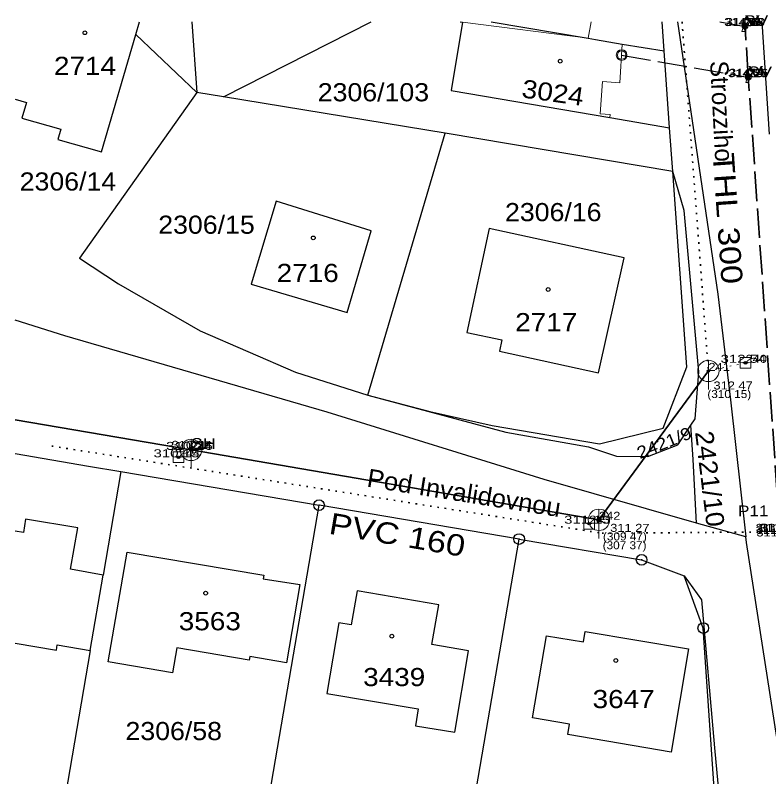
# Model space of a CAD drawing. Extents: x -652394 to -652006, y -1024262 to -1023975.
# Drawn here: x -652393.6 to -652323, y -1024046.7 to -1023975.3 of the extents above; entities that cross this region are included whole.
import ezdxf
from ezdxf.enums import TextEntityAlignment as Align

# ---------------------------------------------------------------- set-up
doc = ezdxf.new("R2010")
doc.units = 0
doc.header["$LTSCALE"] = 0.46
doc.header["$PDMODE"] = 32
doc.header["$PDSIZE"] = 0.23
doc.linetypes.add('DOTTED', pattern=[1.5, 0.3, -1.2])
doc.linetypes.add('LONG_DASHED', pattern=[7.5, 6, -1.5])
for name, color, linetype in [('1', 7, 'Continuous'), ('17', 7, 'Continuous'), ('18', 7, 'Continuous'), ('2', 7, 'Continuous'), ('3', 7, 'Continuous'), ('4', 7, 'Continuous')]:
    doc.layers.add(name, color=color, linetype=linetype)
for name, color, linetype, lineweight in [('10', 7, 'Continuous', 13), ('12', 7, 'Continuous', 13), ('35', 7, 'LONG_DASHED', 35), ('36', 7, 'DOTTED', 35), ('45', 7, 'Continuous', 35), ('46', 7, 'DOTTED', 35), ('50', 7, 'LONG_DASHED', 25), ('63', 7, 'Continuous', 25)]:
    doc.layers.add(name, color=color, linetype=linetype, lineweight=lineweight)

msp = doc.modelspace()

# ---------------------------------------------------------------- linework, layer by layer
at = {"layer": '1'}
for p in [(-652325.34, -1023976.33), (-652325.2, -1023976.32), (-652324.98, -1023981.12), (-652324.89, -1023981.08), (-652325.15, -1024007.88), (-652328.63, -1024008.64), (-652377.1, -1024015.94), (-652377.08, -1024016.04), (-652378.26, -1024016.73), (-652339.8, -1024022.95), (-652338.88, -1024022.59)]:
    msp.add_point(p, dxfattribs=at)
at = {"layer": '10'}
for p, q in [((-652328.63, -1024007.64), (-652328.63, -1024010.388)), ((-652324.9, -1024007.88), (-652325.4, -1024007.88)), ((-652377.08, -1024015.04), (-652377.08, -1024017.788)), ((-652378.01, -1024016.73), (-652378.51, -1024016.73)), ((-652338.88, -1024021.59), (-652338.88, -1024024.338)), ((-652339.55, -1024022.95), (-652340.05, -1024022.95))]:
    msp.add_line(p, q, dxfattribs=at)
for points in [[(-652325.19, -1023976.83), (-652325.49, -1023975.83), (-652325.19, -1023975.83), (-652325.49, -1023976.83)], [(-652324.83, -1023981.62), (-652325.13, -1023980.62), (-652324.83, -1023980.62), (-652325.13, -1023981.62)], [(-652324.65, -1024007.38), (-652325.65, -1024007.38), (-652325.65, -1024008.38), (-652324.65, -1024008.38)], [(-652377.76, -1024016.23), (-652378.76, -1024016.23), (-652378.76, -1024017.23), (-652377.76, -1024017.23)], [(-652339.3, -1024022.45), (-652340.3, -1024022.45), (-652340.3, -1024023.45), (-652339.3, -1024023.45)]]:
    msp.add_lwpolyline(points, close=True, dxfattribs=at)
for centre in [(-652328.63, -1024008.641), (-652377.08, -1024016.041), (-652338.88, -1024022.591)]:
    msp.add_circle(centre, 1.0002, dxfattribs=at)
at = {"layer": '12'}
for centre, radius in [((-652325.2, -1023976.32), 0.3), ((-652325.2, -1023976.32), 0.2), ((-652325.2, -1023976.32), 0.1), ((-652336.754, -1023979.044), 0.5), ((-652336.754, -1023979.044), 0.4), ((-652324.89, -1023981.08), 0.3), ((-652324.89, -1023981.08), 0.2), ((-652324.89, -1023981.08), 0.1)]:
    msp.add_circle(centre, radius, dxfattribs=at)
at = {"layer": '35'}
msp.add_line((-652325.2, -1023976.32), (-652325.218, -1023975.941), dxfattribs=at)
msp.add_lwpolyline([(-652321.94, -1024023.7), (-652324.89, -1023981.08), (-652325.2, -1023976.32)], dxfattribs=at)
at = {"layer": '36'}
msp.add_lwpolyline([(-652390.132, -1024015.68), (-652338.593, -1024023.847), (-652322.39, -1024023.72)], dxfattribs=at)
at = {"layer": '45'}
for p, q in [((-652328.63, -1024008.64), (-652338.88, -1024022.59)), ((-652377.08, -1024016.04), (-652393.553, -1024013.212)), ((-652338.88, -1024022.59), (-652377.08, -1024016.04))]:
    msp.add_line(p, q, dxfattribs=at)
at = {"layer": '46'}
msp.add_line((-652331.095, -1023975.941), (-652328.63, -1024008.64), dxfattribs=at)
at = {"layer": '50'}
for p, q in [((-652327.547, -1023975.941), (-652325.34, -1023976.33)), ((-652325.34, -1023976.33), (-652325.2, -1023976.32)), ((-652336.754, -1023979.044), (-652324.98, -1023981.12)), ((-652324.89, -1023981.08), (-652324.98, -1023981.12))]:
    msp.add_line(p, q, dxfattribs=at)
at = {"layer": '50', "linetype": 'DOTTED', "lineweight": 13}
for p, q in [((-652325.15, -1024007.88), (-652328.63, -1024008.64)), ((-652378.26, -1024016.73), (-652377.08, -1024016.04)), ((-652339.8, -1024022.95), (-652338.88, -1024022.59))]:
    msp.add_line(p, q, dxfattribs=at)
at = {"layer": '63'}
for p, q in [((-652382.27, -1023977.13), (-652381.922, -1023975.941)), ((-652377.024, -1023975.941), (-652376.54, -1023982.54)), ((-652374.06, -1023982.95), (-652360.225, -1023975.941)), ((-652332.78, -1023978.64), (-652332.971, -1023975.941)), ((-652322.92, -1023986.45), (-652323.6, -1023975.941)), ((-652382.27, -1023977.13), (-652376.54, -1023982.54)), ((-652332.26, -1023985.85), (-652332.78, -1023978.64)), ((-652376.54, -1023982.54), (-652387.54, -1023998.06)), ((-652374.06, -1023982.95), (-652376.54, -1023982.54)), ((-652353.29, -1023986.36), (-652374.06, -1023982.95)), ((-652331.96, -1023989.97), (-652332.26, -1023985.85)), ((-652360.54, -1024010.92), (-652353.29, -1023986.36)), ((-652331.96, -1023989.97), (-652353.29, -1023986.36)), ((-652330.06, -1024016.95), (-652330.27, -1024013.72)), ((-652383.67, -1024018.07), (-652385.33, -1024027.79)), ((-652383.67, -1024018.07), (-652365.1, -1024021.22)), ((-652371.82, -1024060.54), (-652365.1, -1024021.22)), ((-652386.53, -1024034.83), (-652385.33, -1024027.79)), ((-652386.53, -1024034.83), (-652390.39, -1024057.39))]:
    msp.add_line(p, q, dxfattribs=at)
at = {"layer": '63', "lineweight": 13}
for p, q in [((-652351.65, -1023975.98), (-652339.88, -1023977.46)), ((-652339.88, -1023977.46), (-652339.61, -1023975.941)), ((-652336.93, -1023981.64), (-652336.69, -1023978.03)), ((-652338.76, -1023984.54), (-652338.56, -1023981.53)), ((-652338.56, -1023981.53), (-652336.93, -1023981.64)), ((-652338.76, -1023984.54), (-652337.83, -1023984.6)), ((-652337.85, -1023984.9), (-652337.83, -1023984.6))]:
    msp.add_line(p, q, dxfattribs=at)
at = {"layer": '63'}
for points in [[(-652351.881, -1023975.941), (-652351.65, -1023975.98), (-652352.73, -1023982.38), (-652337.85, -1023984.9), (-652332.26, -1023985.85)], [(-652348.973, -1023975.941), (-652339.88, -1023977.46), (-652339.19, -1023977.58), (-652336.69, -1023978.03), (-652332.78, -1023978.64)], [(-652331.533, -1023975.941), (-652327.76, -1024001.46), (-652326.57, -1024011.35), (-652325.11, -1024024.18)], [(-652393.553, -1023983.17), (-652392.5, -1023983.48), (-652392.92, -1023984.96), (-652389.28, -1023985.98), (-652389.56, -1023986.95), (-652385.48, -1023988.11), (-652382.27, -1023977.13)], [(-652360.54, -1024010.92), (-652354.73, -1024012.44), (-652348.87, -1024013.74), (-652338.82, -1024015.47), (-652332.85, -1024013.99), (-652330.64, -1024008.25), (-652331.96, -1023989.97)], [(-652330.27, -1024013.72), (-652329.87, -1024013.12), (-652329.53, -1024008.72), (-652330.89, -1023993.61), (-652331.96, -1023989.97)], [(-652387.54, -1023998.06), (-652383.88, -1024000.49), (-652376.22, -1024004.87), (-652367.29, -1024008.75), (-652360.54, -1024010.92)], [(-652329.73, -1024022.9), (-652344, -1024018.8), (-652364.33, -1024012.51), (-652388.9, -1024005.35), (-652393.553, -1024003.886)], [(-652360.54, -1024010.92), (-652347.61, -1024014.39), (-652339.85, -1024015.74), (-652337.24, -1024016.62), (-652334.29, -1024016.67), (-652331.5, -1024015.55), (-652330.27, -1024013.72)], [(-652393.553, -1024016.385), (-652386.69, -1024017.55), (-652383.67, -1024018.07)], [(-652325.11, -1024024.18), (-652329.73, -1024022.9), (-652330.06, -1024016.95)], [(-652353.09, -1024063.72), (-652346.36, -1024024.39), (-652365.1, -1024021.22)], [(-652385.33, -1024027.79), (-652388.37, -1024027.22), (-652387.69, -1024023.34), (-652392.6, -1024022.53), (-652392.79, -1024023.78), (-652393.553, -1024023.654)], [(-652346.36, -1024024.39), (-652334.88, -1024026.34), (-652330.91, -1024027.84)], [(-652313.58, -1024101.21), (-652314.61, -1024096.94), (-652318.74, -1024074.97), (-652320.04, -1024057.03), (-652325.05, -1024024.73), (-652325.11, -1024024.18)], [(-652330.91, -1024027.84), (-652329.29, -1024030.08), (-652328.05, -1024043.94), (-652325.76, -1024068.66)], [(-652326.68, -1024068.2), (-652329.11, -1024032.73), (-652330.91, -1024027.84)], [(-652393.553, -1024034.141), (-652389.7, -1024034.79), (-652389.62, -1024034.31), (-652386.53, -1024034.83)]]:
    msp.add_lwpolyline(points, dxfattribs=at)
at = {"layer": '63', "lineweight": 13}
for points in [[(-652352.73, -1023982.38), (-652337.85, -1023984.9), (-652337.83, -1023984.6), (-652338.76, -1023984.54), (-652338.56, -1023981.53), (-652336.93, -1023981.64), (-652336.69, -1023978.03), (-652339.19, -1023977.58), (-652339.88, -1023977.46), (-652351.65, -1023975.98)], [(-652353.29, -1023986.36), (-652374.06, -1023982.95), (-652376.54, -1023982.54), (-652387.54, -1023998.06), (-652383.88, -1024000.49), (-652376.22, -1024004.87), (-652367.29, -1024008.75), (-652360.54, -1024010.92)], [(-652348.87, -1024013.74), (-652338.82, -1024015.47), (-652332.85, -1024013.99), (-652330.64, -1024008.25), (-652331.96, -1023989.97), (-652353.29, -1023986.36), (-652360.54, -1024010.92), (-652354.73, -1024012.44)], [(-652360.54, -1024010.92), (-652347.61, -1024014.39), (-652339.85, -1024015.74), (-652337.24, -1024016.62), (-652334.29, -1024016.67), (-652331.5, -1024015.55), (-652330.27, -1024013.72), (-652329.87, -1024013.12), (-652329.53, -1024008.72), (-652330.89, -1023993.61), (-652331.96, -1023989.97), (-652330.64, -1024008.25), (-652332.85, -1024013.99), (-652338.82, -1024015.47), (-652348.87, -1024013.74), (-652354.73, -1024012.44)], [(-652362.46, -1024003.16), (-652360.21, -1023995.53), (-652369.12, -1023992.75), (-652371.47, -1024000.5)], [(-652362.46, -1024003.16), (-652371.47, -1024000.5), (-652369.12, -1023992.75), (-652360.21, -1023995.53)], [(-652371.47, -1024000.5), (-652362.46, -1024003.16), (-652360.21, -1023995.53), (-652369.12, -1023992.75)], [(-652347.98, -1024005.74), (-652351.27, -1024005.05), (-652349.17, -1023995.3), (-652336.52, -1023998.03), (-652338.91, -1024008.81), (-652348.2, -1024006.79)], [(-652347.98, -1024005.74), (-652348.2, -1024006.79), (-652338.91, -1024008.81), (-652336.52, -1023998.03), (-652349.17, -1023995.3), (-652351.27, -1024005.05)], [(-652349.17, -1023995.3), (-652351.27, -1024005.05), (-652347.98, -1024005.74), (-652348.2, -1024006.79), (-652338.91, -1024008.81), (-652336.52, -1023998.03)], [(-652386.53, -1024034.83), (-652390.39, -1024057.39), (-652383.22, -1024058.61), (-652371.82, -1024060.54), (-652365.1, -1024021.22), (-652383.67, -1024018.07), (-652385.33, -1024027.79)], [(-652346.36, -1024024.39), (-652365.1, -1024021.22), (-652371.82, -1024060.54), (-652363.58, -1024061.94), (-652353.09, -1024063.72)], [(-652329.11, -1024032.73), (-652330.91, -1024027.84), (-652334.88, -1024026.34), (-652346.36, -1024024.39), (-652353.09, -1024063.72), (-652343.94, -1024065.27), (-652343.25, -1024065.4), (-652326.68, -1024068.2)], [(-652383.08, -1024025.62), (-652384.85, -1024035.91), (-652378.82, -1024036.93), (-652378.42, -1024034.58), (-652371.63, -1024035.73), (-652371.58, -1024035.4), (-652368.13, -1024035.98), (-652366.89, -1024028.64), (-652370.32, -1024028.12), (-652370.27, -1024027.78)], [(-652383.08, -1024025.62), (-652370.27, -1024027.78), (-652370.32, -1024028.12), (-652366.89, -1024028.64), (-652368.13, -1024035.98), (-652371.58, -1024035.4), (-652371.63, -1024035.73), (-652378.42, -1024034.58), (-652378.82, -1024036.93), (-652384.85, -1024035.91)], [(-652383.08, -1024025.62), (-652384.85, -1024035.91), (-652378.82, -1024036.93), (-652378.42, -1024034.58), (-652371.63, -1024035.73), (-652371.58, -1024035.4), (-652368.13, -1024035.98), (-652366.89, -1024028.64), (-652370.32, -1024028.12), (-652370.27, -1024027.78)], [(-652325.76, -1024068.66), (-652328.05, -1024043.94), (-652329.29, -1024030.08), (-652330.91, -1024027.84), (-652329.11, -1024032.73), (-652326.68, -1024068.2)], [(-652361.52, -1024029.23), (-652362.08, -1024032.43), (-652363.24, -1024032.23), (-652364.36, -1024038.87), (-652355.8, -1024040.31), (-652356.06, -1024041.88), (-652352.37, -1024042.48), (-652351.1, -1024034.85), (-652354.52, -1024034.27), (-652353.89, -1024030.55)], [(-652361.52, -1024029.23), (-652353.89, -1024030.55), (-652354.52, -1024034.27), (-652351.1, -1024034.85), (-652352.37, -1024042.48), (-652356.06, -1024041.88), (-652355.8, -1024040.31), (-652364.36, -1024038.87), (-652363.24, -1024032.23), (-652362.08, -1024032.43)], [(-652364.36, -1024038.87), (-652355.8, -1024040.31), (-652356.06, -1024041.88), (-652352.37, -1024042.48), (-652351.1, -1024034.85), (-652354.52, -1024034.27), (-652353.89, -1024030.55), (-652361.52, -1024029.23), (-652362.08, -1024032.43), (-652363.24, -1024032.23)], [(-652341.64, -1024041.73), (-652345.1, -1024041.14), (-652343.79, -1024033.45), (-652340.34, -1024034.02), (-652340.18, -1024033.04), (-652330.5, -1024034.67), (-652332.13, -1024044.36), (-652341.8, -1024042.71)], [(-652341.64, -1024041.73), (-652341.8, -1024042.71), (-652332.13, -1024044.36), (-652330.5, -1024034.67), (-652340.18, -1024033.04), (-652340.34, -1024034.02), (-652343.79, -1024033.45), (-652345.1, -1024041.14)], [(-652332.13, -1024044.36), (-652330.5, -1024034.67), (-652340.18, -1024033.04), (-652340.34, -1024034.02), (-652343.79, -1024033.45), (-652345.1, -1024041.14), (-652341.64, -1024041.73), (-652341.8, -1024042.71)]]:
    msp.add_lwpolyline(points, close=True, dxfattribs=at)
at = {"layer": '63'}
for points in [[(-652362.46, -1024003.16), (-652360.21, -1023995.53), (-652369.12, -1023992.75), (-652371.47, -1024000.5)], [(-652347.98, -1024005.74), (-652348.2, -1024006.79), (-652338.91, -1024008.81), (-652336.52, -1023998.03), (-652349.17, -1023995.3), (-652351.27, -1024005.05)], [(-652383.08, -1024025.62), (-652370.27, -1024027.78), (-652370.32, -1024028.12), (-652366.89, -1024028.64), (-652368.13, -1024035.98), (-652371.58, -1024035.4), (-652371.63, -1024035.73), (-652378.42, -1024034.58), (-652378.82, -1024036.93), (-652384.85, -1024035.91)], [(-652361.52, -1024029.23), (-652362.08, -1024032.43), (-652363.24, -1024032.23), (-652364.36, -1024038.87), (-652355.8, -1024040.31), (-652356.06, -1024041.88), (-652352.37, -1024042.48), (-652351.1, -1024034.85), (-652354.52, -1024034.27), (-652353.89, -1024030.55)], [(-652341.64, -1024041.73), (-652345.1, -1024041.14), (-652343.79, -1024033.45), (-652340.34, -1024034.02), (-652340.18, -1024033.04), (-652330.5, -1024034.67), (-652332.13, -1024044.36), (-652341.8, -1024042.71)]]:
    msp.add_lwpolyline(points, close=True, dxfattribs=at)
for centre, radius in [((-652387.0268, -1023976.9592), 0.175), ((-652342.5068, -1023979.6192), 0.175), ((-652365.6368, -1023996.1792), 0.175), ((-652343.6368, -1024001.0092), 0.175), ((-652365.1, -1024021.2199), 0.5), ((-652365.1, -1024021.2199), 0.0303), ((-652346.36, -1024024.3899), 0.5), ((-652346.36, -1024024.3899), 0.0303), ((-652334.88, -1024026.3399), 0.5), ((-652334.88, -1024026.3399), 0.0303), ((-652375.7168, -1024029.4592), 0.175), ((-652329.11, -1024032.7299), 0.5), ((-652329.11, -1024032.7299), 0.0303), ((-652358.2768, -1024033.4892), 0.175), ((-652337.2968, -1024035.7692), 0.175)]:
    msp.add_circle(centre, radius, dxfattribs=at)

# ---------------------------------------------------------------- texts
at = {"layer": '17', "width": 1.2}
for s, rotation, p in [('THL 300', 273.959, (-652327.8132, -1023994.4229)), ('PVC 160', 350.189, (-652357.9319, -1024024.9753))]:
    msp.add_text(s, height=2, rotation=rotation, dxfattribs=at).set_placement(p, align=Align.CENTER)
at = {"layer": '18', "width": 1.2}
msp.add_text('P11', height=1, dxfattribs=at).set_placement((-652324.425, -1024022.248), align=Align.CENTER)
at = {"layer": '2'}
for s, width, p in [('76', 1.3, (-652325.34, -1023976.33)), ('75', 1.3, (-652325.2, -1023976.32)), ('73', 1.3, (-652324.98, -1023981.12)), ('74', 1.3, (-652324.89, -1023981.08)), ('240', 1.2, (-652325.15, -1024007.88)), ('241', 1.2, (-652328.63, -1024008.64)), ('71', 1.3, (-652377.1, -1024015.94)), ('245', 1.2, (-652377.08, -1024016.04)), ('244', 1.2, (-652378.26, -1024016.73)), ('243', 1.2, (-652339.8, -1024022.95)), ('242', 1.2, (-652338.88, -1024022.59))]:
    msp.add_text(s, height=0.75, dxfattribs=dict(at, width=width)).set_placement(p)
at = {"layer": '3'}
for s, width, p in [('314 58 ', 1.2, (-652325.138, -1023976.33)), ('314 60 ', 1.2, (-652324.998, -1023976.32)), ('314 25 ', 1.2, (-652324.778, -1023981.12)), ('314 26 ', 1.2, (-652324.688, -1023981.08)), ('312 54 ', 1.4, (-652325.15, -1024007.88)), ('312 47 ', 1.2, (-652326.146, -1024010.379)), ('(310 15)', 1.1, (-652326.673, -1024011.179)), ('310 27 ', 1.2, (-652376.898, -1024015.94)), ('310 24 ', 1.4, (-652377.08, -1024016.04)), ('310 15 ', 1.4, (-652378.26, -1024016.73)), ('311 15 ', 1.4, (-652339.8, -1024022.95)), ('311 27 ', 1.2, (-652335.818, -1024023.716)), ('311 74 ', 1.2, (-652322.188, -1024023.72)), ('311 74 ', 1.2, (-652321.908, -1024023.72)), ('311 76 ', 1.2, (-652321.738, -1024023.7)), ('311 83 ', 1.2, (-652321.719, -1024023.709)), ('(309 47)', 1.1, (-652336.449, -1024024.521)), ('311 74 ', 1.2, (-652322.188, -1024023.91)), ('311 74 ', 1.2, (-652322.128, -1024024.15)), ('(307 37)', 1.1, (-652336.477, -1024025.347))]:
    msp.add_text(s, height=0.75, dxfattribs=dict(at, width=width)).set_placement(p, align=Align.CENTER)
at = {"layer": '4'}
for s, width, p in [('SV', 1.3, (-652325.34, -1023976.33)), ('V', 1.55, (-652325.2, -1023976.32)), ('SV', 1.3, (-652324.98, -1023981.12)), ('V', 1.55, (-652324.89, -1023981.08)), ('SH', 1.25, (-652377.1, -1024015.94))]:
    msp.add_text(s, height=1, dxfattribs=dict(at, width=width)).set_placement(p)
at = {"layer": '63'}
for s, width, p in [('2714', 1.15, (-652389.927, -1023980.91)), ('2306/103', 1.1, (-652365.22, -1023983.38)), ('2306/14', 1.1, (-652393.138, -1023991.74)), ('2306/16', 1.1, (-652347.678, -1023994.61)), ('2306/15', 1.1, (-652380.158, -1023995.79)), ('2716', 1.15, (-652369.067, -1024000.31)), ('2717', 1.15, (-652346.727, -1024004.92)), ('3563', 1.15, (-652378.237, -1024032.94)), ('3439', 1.15, (-652360.967, -1024038.17)), ('3647', 1.15, (-652339.477, -1024040.23)), ('2306/58', 1.1, (-652383.228, -1024043.23))]:
    msp.add_text(s, height=1.7, dxfattribs=dict(at, width=width)).set_placement(p)
msp.add_text('Strozziho', height=1.7, rotation=273, dxfattribs=at).set_placement((-652328.477, -1023979.622))
for s, height, rotation, width, p in [('3024', 1.7, 352, 1.15, (-652346.191, -1023983.002)), ('2421/9', 1.139, 22, 1.15, (-652335.04, -1024016.907)), ('2421/10', 1.7, 277, 1.1, (-652329.883, -1024014.363)), ('Pod Invalidovnou', 1.7, 351, 1.05, (-652360.69, -1024019.469))]:
    msp.add_text(s, height=height, rotation=rotation, dxfattribs=dict(at, width=width)).set_placement(p)

doc.saveas('drawing.dxf')
